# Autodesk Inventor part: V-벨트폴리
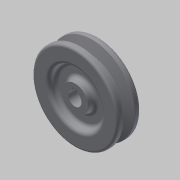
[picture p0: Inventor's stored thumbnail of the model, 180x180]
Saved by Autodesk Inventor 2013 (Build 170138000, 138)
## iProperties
Created: 2015-02
Part Number: V-벨트폴리
Material: 일반
Document SubType Name: Modeling
Designer: Administrator
Density: 1 g/cm^3
Author: Administrator
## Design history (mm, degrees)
sketch "스케치1"
  geometry: L1 (0, 0)-(50, 0); L2 (0, 11)-(6, 11); L3 (6, 11)-(6, 21.5); L4 (6, 21.5)-(0, 21.5); L5 (0, 21.5)-(0, 35.2); L6 (0, 35.2)-(4.675, 35.2); L7 (4.675, 35.2)-(7.426, 26.2); L8 (7.426, 26.2)-(11.574, 26.2); L9 (11.574, 26.2)-(14.325, 35.2); L10 (14.325, 35.2)-(19, 35.2); L11 (19, 35.2)-(19, 21.5); L12 (19, 21.5)-(13, 21.5); L13 (13, 21.5)-(13, 11); L14 (13, 11)-(25, 11); L15 (25, 11)-(25, 5.5); L16 (25, 5.5)-(0, 5.5); L17 (0, 5.5)-(0, 11); L18 (9.5, 47.5)-(9.5, 17.5); L19 (-5.5, 32.5)-(24.5, 32.5); 3 further points
  constraints: 38 end point, 13 parallel, 2 horizontal alignment, 2 midpoint, 2 perpendicular, 2 point on line, 2 vertical alignment, 1 collinear, 1 horizontal, 1 other
  dimensions: "d0" = 50 distance of L1.start L1.end; "d1" = 6 distance of L2.start L2.end; "d2" = 25 distance between parallel lines of L15 L17; "d3" = 6 distance of L11.end L12.end; "d4" = 11 diameter of L16 L1; "d5" = 22 diameter of L14 L1; "d6" = 30 distance of L18.start L18.end; "d7" = 30 distance of L19.start L19.end; "d8" = 9.5 distance between parallel lines of L18 L5; "d9" = 19 distance between parallel lines of L11 L5; "d10" = 34 deg angle of L9 L7; "d11" = 65 diameter of L19 L1; "d12" = 6.3 distance between parallel lines of L19 L8; "d13" = 2.7 distance between parallel lines of L19 L10; "d14" = 2.7 distance between parallel lines of L19 L6; "d15" = 8 distance of point (13.5, 32.5) point (5.5, 32.5); "d16" = 43 diameter of L4 L1; "d17" = 43 diameter of L12 L1; "d18" = 22 diameter of L2 L1
revolve "회전1" sketch "스케치1" stored, may be unused: angle "d19" = 90 deg
sketch "스케치2"
  geometry: L1 (-2, 7.3)-(2, 7.3); L2 (2, 7.3)-(2, 3.3); L3 (2, 3.3)-(-2, 3.3); L4 (-2, 3.3)-(-2, 7.3); C1 r 11 at (0, 0) reference; 1 further point
  constraints: 8 end point, 2 parallel, 1 horizontal, 1 midpoint, 1 perpendicular, 1 vertical alignment
  dimensions: "d20" = 7.3 distance from line of L1 C1.centre; "d21" = 4 distance between parallel lines of L2 L4; "d22" = 4 distance between parallel lines of L1 L3
extrude "돌출1" cut sketch "스케치2" distance "d23" = 25; taper "d24" = 0 deg
fillet "모깎기1" dims "d25" = 0.5
fillet "모깎기2" dims "d26" = 2
fillet "모깎기3" dims "d27" = 1
fillet "모깎기4" dims "d28" = 2
fillet "모깎기5" dims "d29" = 0.5
fillet "모깎기6" dims "d30" = 1
fillet "모깎기7" dims "d31" = 3
node "솔리드1"
